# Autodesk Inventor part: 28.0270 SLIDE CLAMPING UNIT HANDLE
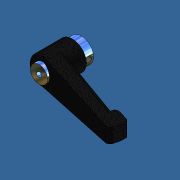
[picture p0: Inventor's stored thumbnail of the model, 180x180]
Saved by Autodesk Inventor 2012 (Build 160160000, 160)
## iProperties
Created: 2007-06
Part Number: 28.0270 SLIDE CLAMPING UNIT HANDLE
Material: Steel
Document SubType Name: Modeling
Designer: Andy Moles
Density: 7.85 g/cm^3
Mass: 126.291 g
Surface Area: 53.9924 cm^2
Volume: 16.088 cm^3
Author: Andy Moles
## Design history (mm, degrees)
feature "Base1"
fillet "Fillet1" dims "d0" = 2.5
thread "Thread1" dims "d1" = 10, "d2" = 0
sketch "Sketch1"
  geometry: L1 (-8.5, 6.5)-(8.5, 6.5) reference; L2 (8.5, 0)-(-8.5, 0) reference; C1 r 2 at (-0.041, 3.25); 1 further point
  constraints: 1 centre point
  dimensions: "d3" = 4 diameter of C1; "d4" = 6.5 distance between parallel lines of L2 L1 (derived); "d5" = 3.25 distance from line of C1.centre L1 (= 0.5 x d4)
extrude "Extrusion1" cut sketch "Sketch1" stored distance "d6" = 10; taper "d7" = 0 deg
thread "Thread2" dims "d8" = 10, "d9" = 0
body "Solid1"
